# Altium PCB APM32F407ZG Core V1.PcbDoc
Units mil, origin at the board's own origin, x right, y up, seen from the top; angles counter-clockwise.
Board outline 2360 x 2125 mil, 2 copper layers (Top Layer, Bottom Layer); 40 components, 124 nets, 388 pads, 216 vias.
Unrouted connection lines stored in the file: 595.
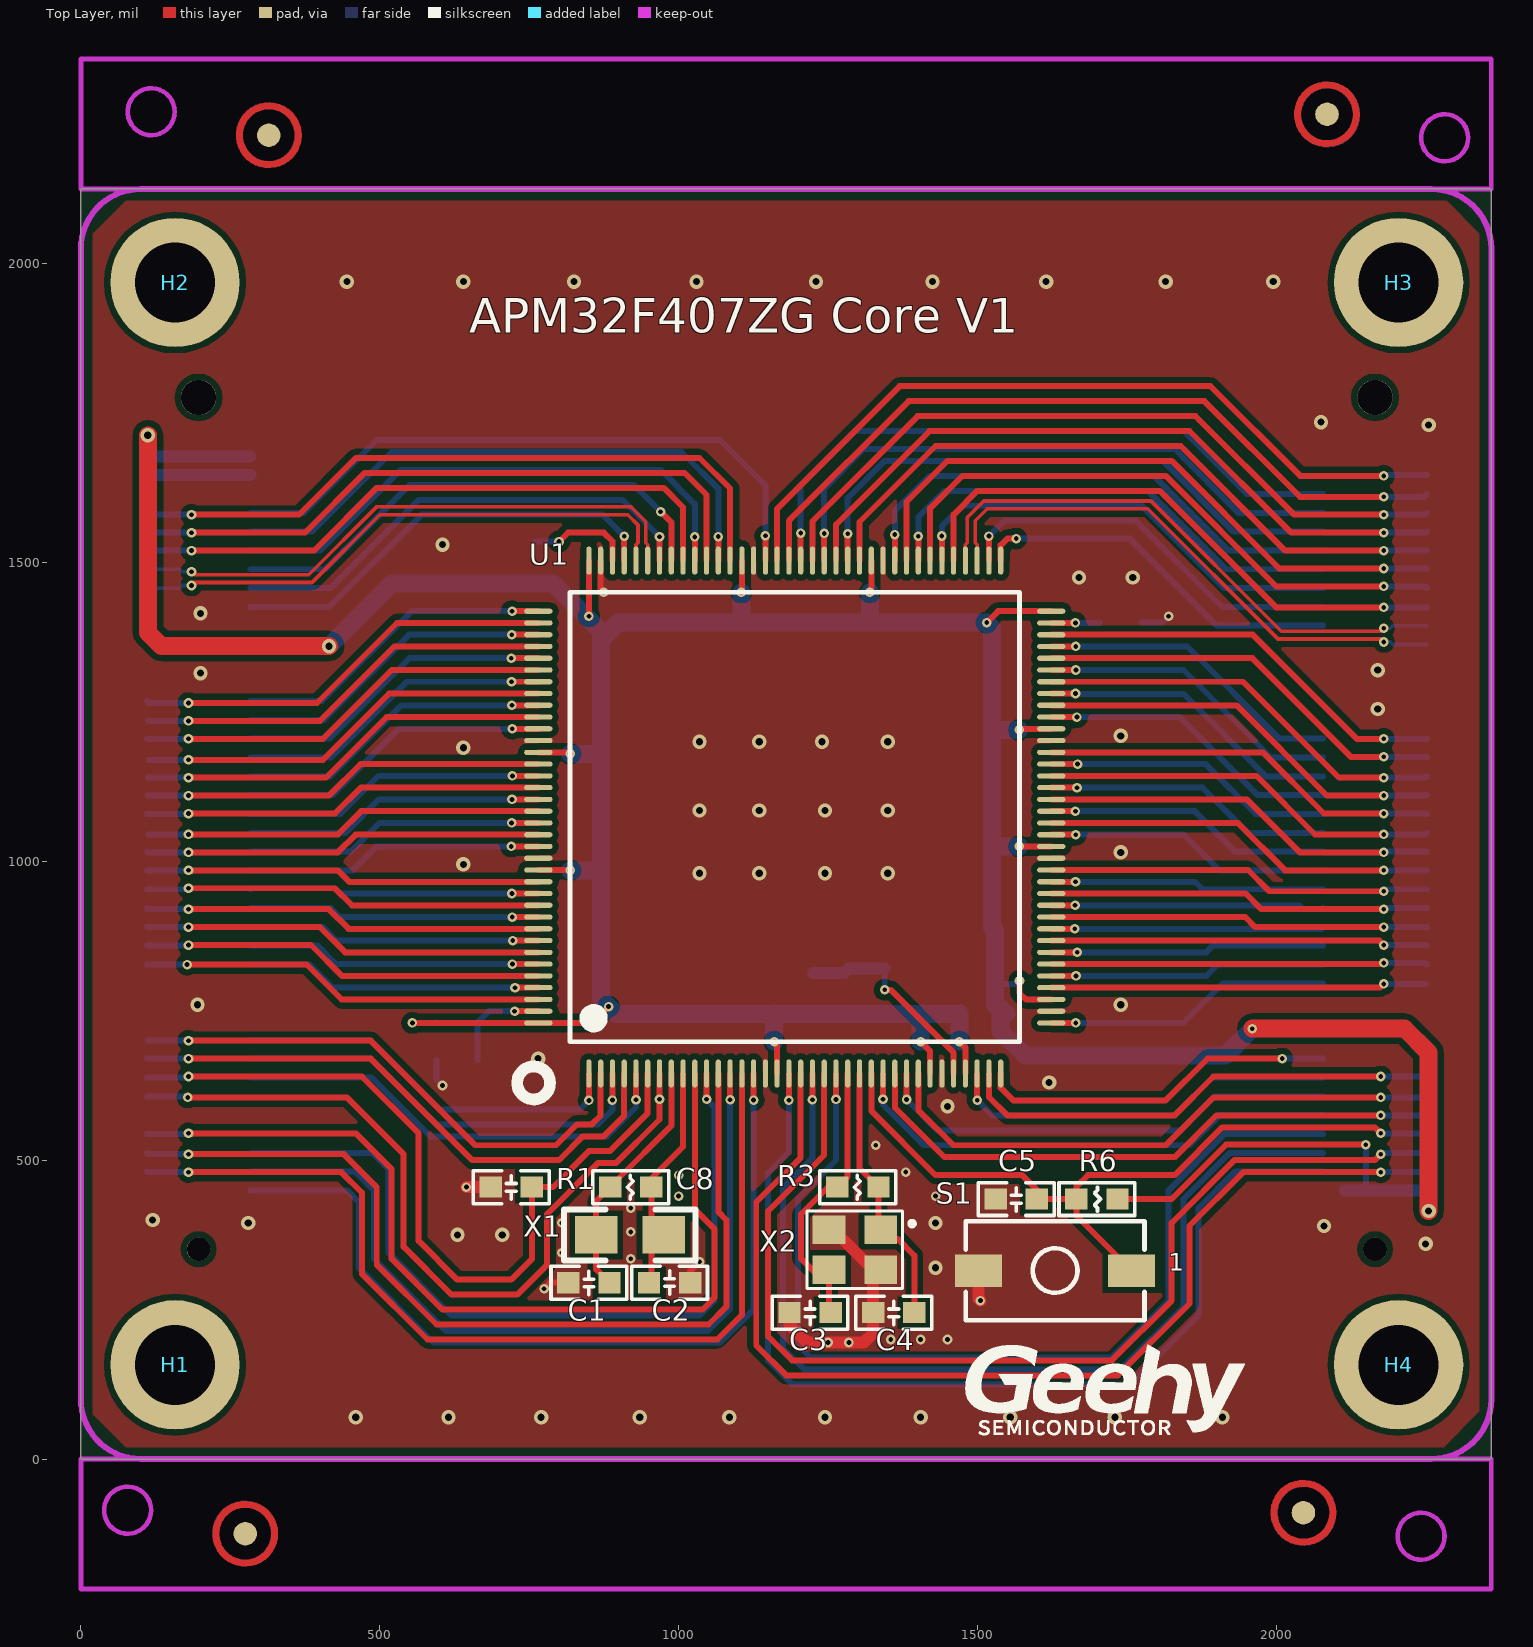
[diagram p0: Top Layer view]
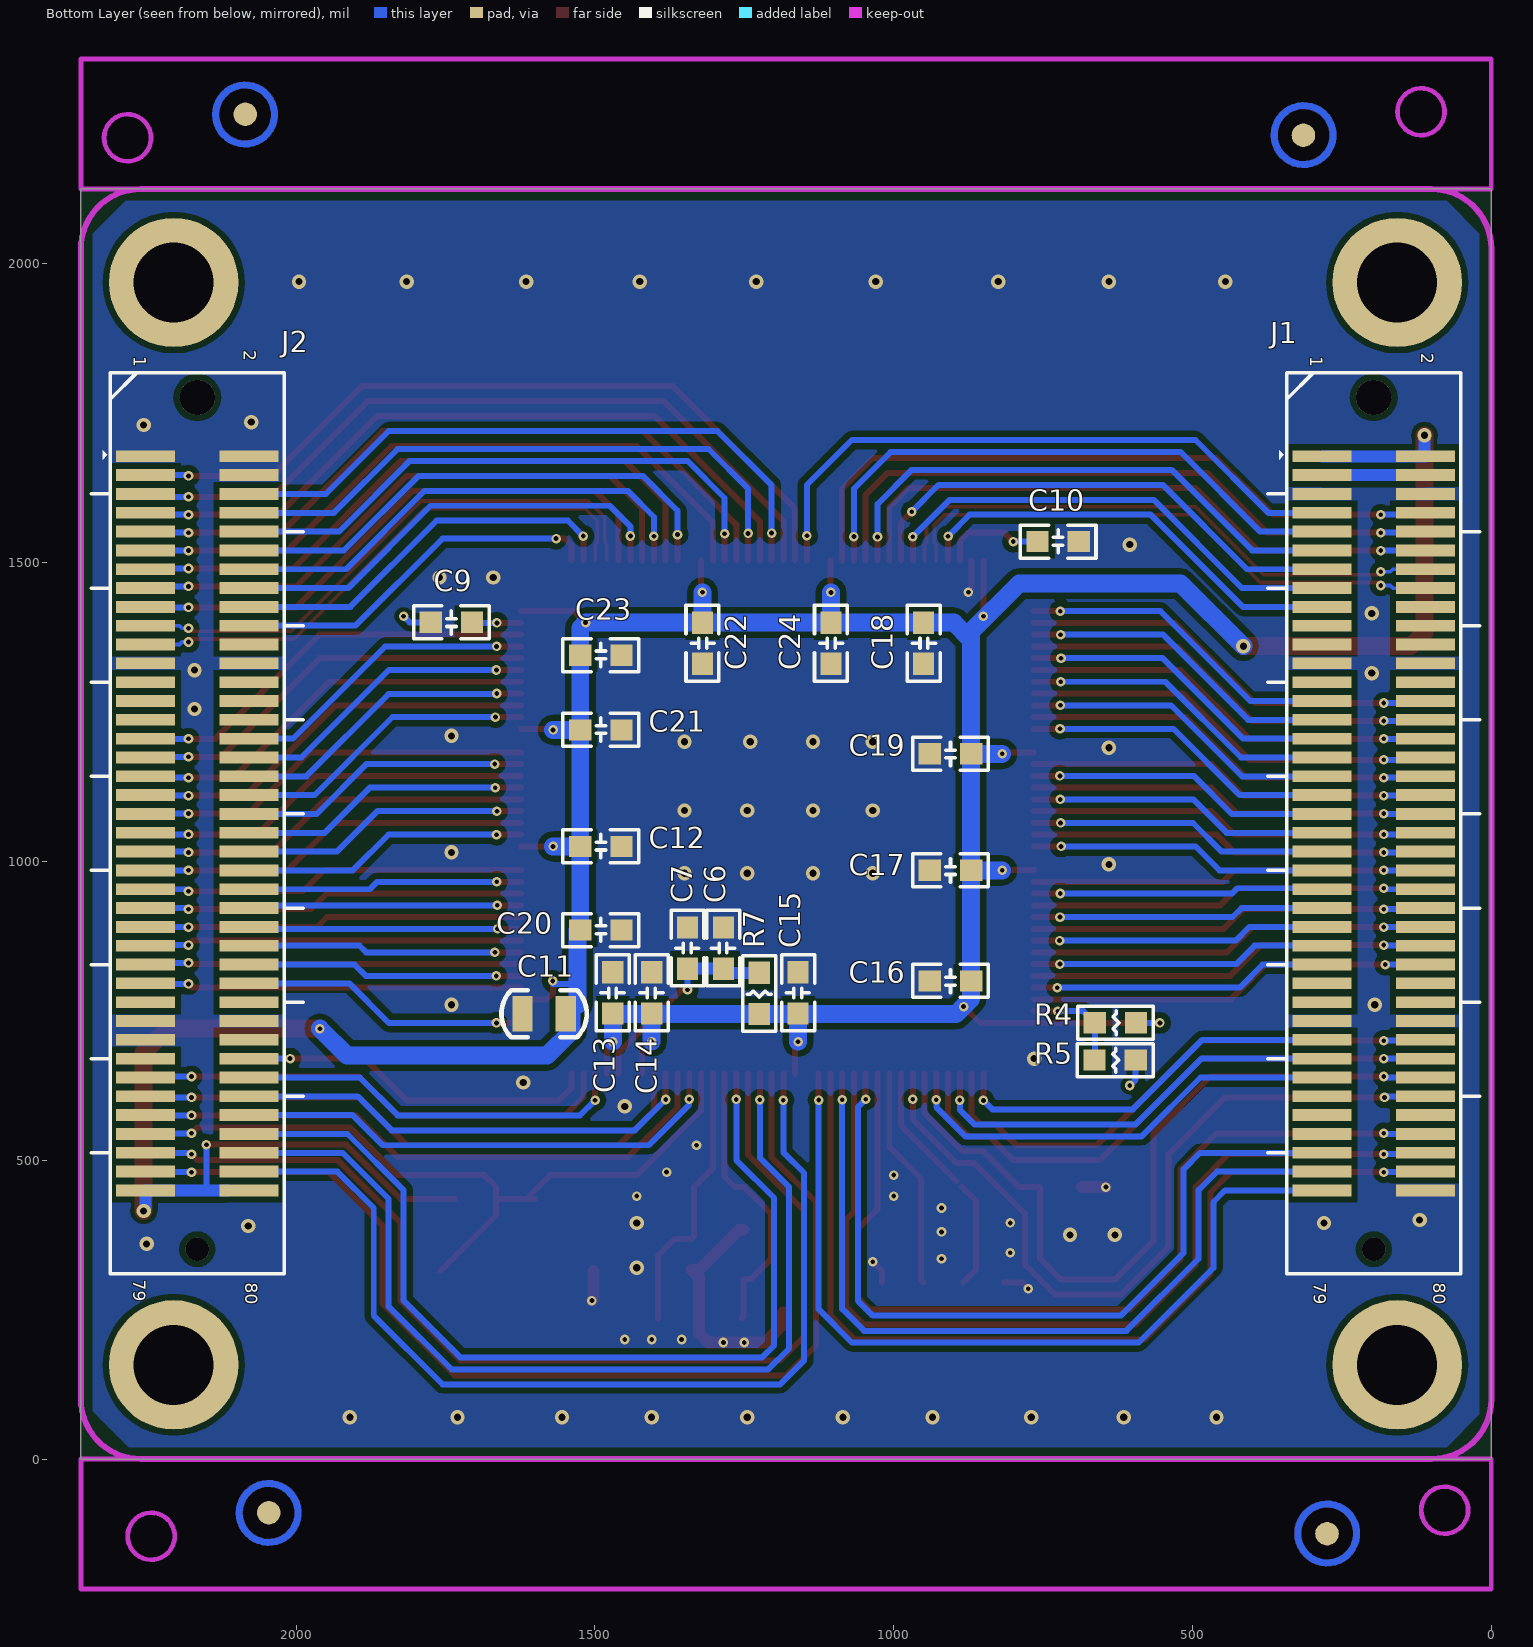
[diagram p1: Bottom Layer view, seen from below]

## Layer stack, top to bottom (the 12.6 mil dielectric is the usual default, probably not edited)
Top Layer: signal copper 1.4
Dielectric: dielectric 12.6, FR-4, Dk 4.8
Bottom Layer: signal copper 1.4

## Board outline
0,2125 0,0 2360,0 2360,2125

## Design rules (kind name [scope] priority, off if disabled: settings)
Clearance Clearance_1 [IsRegion] p1: gap=10
Clearance [All] p2: gap=6
DiffPairsRouting [All] p1: maxlimit=10 minlimit=1 mostfreqgap=7 maxuncoupledlength=500
HoleSize [All] p1: absolutevalues=TRUE maxlimit=1000 minlimit=1 maxpercent=80.000 minpercent=20.000
MinimumSolderMaskSliver [All] p1: minsoldermaskwidth=0.1
PolygonConnect [All] p1: connectstyle=Direct reliefconductorwidth=10 reliefentries=4 polygonreliefangle="90 Angle" airgapwidth=10
RoutingVias [All] p1: holewidth=8 width=16 viastyle="Through Hole" minholewidth=1 minwidth=1 maxholewidth=28 maxwidth=50
SilkToSilkClearance [All] p1: silktosilkclearance=1
SilkToSolderMaskClearance [IsPad] p1: minsilkscreentomaskgap=0.1 clearancetoexposedcopper=TRUE
SolderMaskExpansion [All] p1: expansion=4
Width [All] p1: maxlimit=100 minlimit=1 preferedwidth=10 minimp=50.000000 maximp=50.000000 favimp=50.000000
23 further rules are at their usual default settings.

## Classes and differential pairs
component class 02_Connect: H1 H2 H3 H4 J1 J2
differential pair class "New Class": OTG_FS OTG_HS
component class 01_MCU: C1 C2 C3 C4 C5 C6 C7 C8 C9 C10 C11 C12 C13 C14 C15 C16 C17 C18 C19 C20 C21 C22 C23 C24 J3 R1 R3 R4 R5 R6 R7 S1 U1 U4 X1 X2
differential pair OTG_FS: +PA12_OTG_FS_P -PA11_OTG_FS_N
differential pair OTG_HS: +PB15_OTG_HS_P -PB14_OTG_HS_N

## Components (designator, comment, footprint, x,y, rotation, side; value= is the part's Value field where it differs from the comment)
C1 "10pF" C0603 850,294.98 r180 top
C2 "10pF" C0603 985,294.98 r0 top
C3 "20pF" C0603 1220,244.98 r180 top
C4 "20pF" C0603 1360,244.98 r180 top
C5 "100nF" C0603 1565,434.98 r180 top
C6 "1uF" C0603 1285,854.98 r90 bottom
C7 "10nF" C0603 1345,854.98 r90 bottom
C8 "100nF" C0603 720,454.98 r180 top
C9 "2.2uF" C0603 1740,1399.98 r0 bottom
C10 "2.2uF" C0603 725,1534.98 r180 bottom
C11 "4.7uF" C0805 1585,744.98 r0 bottom
C12 "100nF" C0603 1490,1024.98 r180 bottom
C13 "100nF" C0603 1470,779.98 r90 bottom
C14 "100nF" C0603 1405,779.98 r90 bottom
C15 "100nF" C0603 1160,779.98 r90 bottom
C16 "100nF" C0603 905,799.98 r0 bottom
C17 "100nF" C0603 905,984.98 r0 bottom
C18 "100nF" C0603 950,1364.98 r270 bottom
C19 "100nF" C0603 905,1179.98 r0 bottom
C20 "100nF" C0603 1490,884.98 r180 bottom
C21 "100nF" C0603 1490,1219.98 r180 bottom
C22 "100nF" C0603 1490,1344.98 r180 bottom
C23 "100nF" C0603 1320,1364.98 r270 bottom
C24 "100nF" C0603 1105,1364.98 r270 bottom
H1 "Value" THC5R5D3R4-M3-PTH#1 975,3804.98 r0 top
H2 "Value" THC5R5D3R4-M3-PTH#2 157.48,2792.5 r0 top
H3 "Value" THC5R5D3R4-M3-PTH#3 1570,3814.98 r0 top
H4 "Value" THC5R5D3R4-M3-PTH#4 1845,3814.98 r0 top
J1 "61082-081402LF" B2B2X40R-0R8-SM-Z-H3R7 196.81,1063.57 r270 bottom locked
J2 "61082-081402LF" B2B2X40R-0R8-SM-Z-H3R7 2165.31,1063.57 r270 bottom
R1 "NC" R0603 920,454.98 r180 top
R3 "NC" R0603 1300,454.98 r180 top
R4 "NC" R0603 629,729.98 r180 bottom
R5 "10K" R0603 629.55,667.54 r180 bottom
R6 "10K" R0603 1700,434.98 r0 top
R7 "0R" R0603 1225,778.98 r270 bottom
S1 "434121025816" SW-SMD-6X3R8X2R5-1 1630,314.98 r180 top
U1 "APM32F407ZG" LQFP-144M 850,644.98 r90 top locked
X1 "32.768KHz" R1206 975,374.98 r180 top
X2 "8MHz" XTAL3225 1295,349.98 r180 top

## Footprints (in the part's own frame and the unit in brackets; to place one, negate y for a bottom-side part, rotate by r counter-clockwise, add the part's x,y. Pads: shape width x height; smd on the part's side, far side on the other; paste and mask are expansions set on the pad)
B2B2X40R-0R8-SM-Z-H3R7 [mm]
  rect 0.5x2.5 smd: 1(-15.6,-2.2) 2(-15.6,2.2) 3(-14.8,-2.2) 4(-14.8,2.2) 5(-14,-2.2) 6(-14,2.2) 7(-13.2,-2.2) 8(-13.2,2.2) 9(-12.4,-2.2) 10(-12.4,2.2) 11(-11.6,-2.2) 12(-11.6,2.2) 13(-10.8,-2.2) 14(-10.8,2.2) 15(-10,-2.2) 16(-10,2.2) 17(-9.2,-2.2) 18(-9.2,2.2) 19(-8.4,-2.2) 20(-8.4,2.2) 21(-7.6,-2.2) 22(-7.6,2.2) 23(-6.8,-2.2) 24(-6.8,2.2) 25(-6,-2.2) 26(-6,2.2) 27(-5.2,-2.2) 28(-5.2,2.2) 29(-4.4,-2.2) 30(-4.4,2.2) 31(-3.6,-2.2) 32(-3.6,2.2) 33(-2.8,-2.2) 34(-2.8,2.2) 35(-2,-2.2) 36(-2,2.2) 37(-1.2,-2.2) 38(-1.2,2.2) 39(-0.4,-2.2) 40(-0.4,2.2) 41(0.4,-2.2) 42(0.4,2.2) 43(1.2,-2.2) 44(1.2,2.2) 45(2,-2.2) 46(2,2.2) 47(2.8,-2.2) 48(2.8,2.2) 49(3.6,-2.2) 50(3.6,2.2) 51(4.4,-2.2) 52(4.4,2.2) 53(5.2,-2.2) 54(5.2,2.2) 55(6,-2.2) 56(6,2.2) 57(6.8,-2.2) 58(6.8,2.2) 59(7.6,-2.2) 60(7.6,2.2) 61(8.4,-2.2) 62(8.4,2.2) 63(9.2,-2.2) 64(9.2,2.2) 65(10,-2.2) 66(10,2.2) 67(10.8,-2.2) 68(10.8,2.2) 69(11.6,-2.2) 70(11.6,2.2) 71(12.4,-2.2) 72(12.4,2.2) 73(13.2,-2.2) 74(13.2,2.2) 75(14,-2.2) 76(14,2.2) 77(14.8,-2.2) 78(14.8,2.2) 79(15.6,-2.2) 80(15.6,2.2)
  round 1.5 hole 1.5: 81(-18.1,0)
  round 1 hole 1: 82(18.1,0)
  silkscreen extent -19.16,-4.5 19.15,4.5, body extent -18.9,-3 18.9,3, height 3.7
C0603 [mm]
  rect 0.95x0.9 smd: 1(-0.875,0) 2(0.875,0)
  silkscreen extent -1.61,-0.7 1.61,0.7, body extent -0.76,-0.41 0.76,0.36, height 0.78
C0805 [mm]
  rect 0.86x1.5 smd: 1(-0.92,0) 2(0.92,0)
  silkscreen extent -1.81,-1 1.81,1, body extent -1,-0.62 1,0.63, height 0.78
LQFP-144M [mm]
  oval 1.2x0.22 smd: 1(0,0) 2(0,-0.5) 3(0,-1) 4(0,-1.5) 5(0,-2) 6(0,-2.5) 7(0,-3) 8(0,-3.5) 9(0,-4) 10(0,-4.5) 11(0,-5) 12(0,-5.5) 13(0,-6) 14(0,-6.5) 15(0,-7) 16(0,-7.5) 17(0,-8) 18(0,-8.5) 19(0,-9) 20(0,-9.5) 21(0,-10) 22(0,-10.5) 23(0,-11) 24(0,-11.5) 25(0,-12) 26(0,-12.5) 27(0,-13) 28(0,-13.5) 29(0,-14) 30(0,-14.5) 31(0,-15) 32(0,-15.5) 33(0,-16) 34(0,-16.5) 35(0,-17) 36(0,-17.5) 73(21.8,-17.5) 74(21.8,-17) 75(21.8,-16.5) 76(21.8,-16) 77(21.8,-15.5) 78(21.8,-15) 79(21.8,-14.5) 80(21.8,-14) 81(21.8,-13.5) 82(21.8,-13) 83(21.8,-12.5) 84(21.8,-12) 85(21.8,-11.5) 86(21.8,-11) 87(21.8,-10.5) 88(21.8,-10) 89(21.8,-9.5) 90(21.8,-9) 91(21.8,-8.5) 92(21.8,-8) 93(21.8,-7.5) 94(21.8,-7) 95(21.8,-6.5) 96(21.8,-6) 97(21.8,-5.5) 98(21.8,-5) 99(21.8,-4.5) 100(21.8,-4) 101(21.8,-3.5) 102(21.8,-3) 103(21.8,-2.5) 104(21.8,-2) 105(21.8,-1.5) 106(21.8,-1) 107(21.8,-0.5) 108(21.8,0)
  oval 0.22x1.2 smd: 37(2.15,-19.65) 38(2.65,-19.65) 39(3.15,-19.65) 40(3.65,-19.65) 41(4.15,-19.65) 42(4.65,-19.65) 43(5.15,-19.65) 44(5.65,-19.65) 45(6.15,-19.65) 46(6.65,-19.65) 47(7.15,-19.65) 48(7.65,-19.65) 49(8.15,-19.65) 50(8.65,-19.65) 51(9.15,-19.65) 52(9.65,-19.65) 53(10.15,-19.65) 54(10.65,-19.65) 55(11.15,-19.65) 56(11.65,-19.65) 57(12.15,-19.65) 58(12.65,-19.65) 59(13.15,-19.65) 60(13.65,-19.65) 61(14.15,-19.65) 62(14.65,-19.65) 63(15.15,-19.65) 64(15.65,-19.65) 65(16.15,-19.65) 66(16.65,-19.65) 67(17.15,-19.65) 68(17.65,-19.65) 69(18.15,-19.65) 70(18.65,-19.65) 71(19.15,-19.65) 72(19.65,-19.65) 109(19.65,2.15) 110(19.15,2.15) 111(18.65,2.15) 112(18.15,2.15) 113(17.65,2.15) 114(17.15,2.15) 115(16.65,2.15) 116(16.15,2.15) 117(15.65,2.15) 118(15.15,2.15) 119(14.65,2.15) 120(14.15,2.15) 121(13.65,2.15) 122(13.15,2.15) 123(12.65,2.15) 124(12.15,2.15) 125(11.65,2.15) 126(11.15,2.15) 127(10.65,2.15) 128(10.15,2.15) 129(9.65,2.15) 130(9.15,2.15) 131(8.65,2.15) 132(8.15,2.15) 133(7.65,2.15) 134(7.15,2.15) 135(6.65,2.15) 136(6.15,2.15) 137(5.65,2.15) 138(5.15,2.15) 139(4.65,2.15) 140(4.15,2.15) 141(3.65,2.15) 142(3.15,2.15) 143(2.65,2.15) 144(2.15,2.15)
  silkscreen extent -1.1,-18.3 20.45,3.05
R0603 [mm]
  rect 0.95x0.9 smd: 1(-0.875,0) 2(0.875,0)
  silkscreen extent -1.61,-0.7 1.61,0.7, body extent -0.82,-0.43 0.88,0.37, height 0.56
R1206 [mm]
  rect 1.8x1.6 smd: 1(0,0) 2(2.865,0)
  silkscreen extent -1.36,-1.08 4.24,1.08
SW-SMD-6X3R8X2R5-1 [mm]
  rect 2x1.4 smd: 1(-3.25,0) 2(3.25,0)
  silkscreen extent -3.8,-2.1 3.8,2.1, body extent -3.65,-1.96 3.65,1.94, height 2.5
THC5R5D3R4-M3-PTH#1 [mm]
  round 5.5 hole 3.4: 1(-20.765,-92.647)
THC5R5D3R4-M3-PTH#2 [mm]
  round 5.5 hole 3.4: 1(0,-20.93)
THC5R5D3R4-M3-PTH#3 [mm]
  round 5.5 hole 3.4: 1(16.122,-46.901)
THC5R5D3R4-M3-PTH#4 [mm]
  round 5.5 hole 3.4: 1(9.137,-92.901)
XTAL3225 [mm]
  rect 1.4x1.2 smd: 1(-1.1,-0.85) 2(1.1,-0.85) 3(1.1,0.85) 4(-1.1,0.85)
  silkscreen extent -2.48,-1.65 2.04,1.65, body extent -1.63,-1.28 1.57,1.22, height 0.91

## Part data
C1 C2: library part 101CC-00365BE.01, "SMD,电容量10pF,额定电压50V,偏差±1pF,材质C0G,0603"
C3 C4: library part 101CC-00471BW.01, "安装方式SMD,电容量20pF,额定电压50V,偏差±5%,材质NPO,0603"
C5 C8 C12 C13 C14 C15 C16 C17 C18 C19 C20 C21 C22 C23 C24: library part 101CC-00003IA.01, "SMD,电容量100nF,额定电压50V,偏差±10%,材质X7R,0603"
C6: library part 101CC-00005IA.01, "SMD,电容量1uF,额定电压50V,偏差±10%,材质X5R,0603"
C7: library part 101CC-00002IA.01, "SMD,电容量10nF,额定电压50V,偏差±10%,材质X7R,0603"
C9 C10: library part 101CC-00009IA.01, "SMD,电容量2.2uF,额定电压25V,偏差±10%,材质X5R,0603"
C11: library part 101CC-00357OD.01, "SMD,电容量4.7uF,额定电压50V,精度±10%,材质X5R,0805"
H1 H2 H3 H4: library part M3-PTH
J1 J2: library part 101NH-00010CO.01, "SMD,座子,封装脚距0.80mm,180度,引脚数目2x40PIN,塑高/针长3.7mm/无,白色"
R1 R3 R4 R7: library part 101RC-00012IA.01, "SMD,阻值0R,精度±1%,0603,额定功率1/10W"
R5 R6: library part 101RC-00003IA.01, "SMD,阻值10K,精度±1%,0603,额定功率1/10W"
S1: library part 101SA-00035BV.01, "安装方式SMD,封装尺寸6.00x3.80x2.50mm,2PIN,装配角度180度,黑色"
U1: library part APM32F407Z
X1: library part XTAL, "Crystal Oscillator"
X2: library part 101XB-00001AN.01, "SMD,材质陶瓷外壳,封装外壳3225,精度±10ppm,震荡频率8MHz"

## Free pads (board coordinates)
  round 39.37 smd: 1(275,-125) 1(314.48,2214.87) 1(2045.52,-89.87) 1(2085,2250)
  round 39.37 smd far side: 6(275,-125) 6(314.48,2214.87) 6(2045.52,-89.87) 6(2085,2250)

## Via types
v1: diameter 16, hole 8, Top Layer to Bottom Layer, 156 vias
v2: diameter 24, hole 12, Top Layer to Bottom Layer, 60 vias

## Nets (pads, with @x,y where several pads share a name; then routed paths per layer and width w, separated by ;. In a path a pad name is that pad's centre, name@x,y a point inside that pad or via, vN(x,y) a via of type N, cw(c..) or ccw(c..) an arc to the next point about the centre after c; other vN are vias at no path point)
+3V3: C11.1 C12.1 C13.1 C14.1 C15.1 C16.1 C17.1 C18.1 C19.1 C20.1 C21.1 C22.1 C23.1 C24.1 J1.1 J1.2 J2.79 J2.80 R4.2 R6.2 R7.2 U1.17 U1.30 U1.33 U1.39 U1.52 U1.62 U1.72 U1.84 U1.95 U1.108 U1.121 U1.131 U1.144 | length 7356.3
  Top Layer w10: v1(554.65,729.63) U1.144 855.65,729.63 v1(883,756.98) ; U1.131 817.95,985.54 v1(818.5,984.98) ; U1.121 816.1,1182.39 v1(818.5,1179.98) ; v1(850,1409.98) U1.108 ; v1(1105,1449.98) 1105.91,1450.89 U1.95 ; v1(1160,698.13) 1164.96,693.17 U1.17 ; v1(1320,1450.1) 1322.44,1452.54 U1.84 ; v1(1405,698.13) 1420.87,682.27 U1.30 ; v1(1470,698.13) 1479.92,688.21 U1.33 ; v1(1515.55,1399.43) 1534.72,1418.61 U1.72 ; v1(1570,1024.98) 1570.08,1024.91 U1.52 ; v1(1570,1219.98) 1571.77,1221.76 U1.62 ; v1(1570.47,799.98) 1570.47,779.51 1580.98,769 U1.39 ; R6.2 1825,434.98 1916,525.98 v1(2150,525.98)
  Top Layer w30: v2(111.97,1713.02) 111.97,1383.02 135,1359.98 v2(415,1359.98) ; v1(1960,719.98) 2215,719.98 2255,679.98 v2(2255,414.98)
  Bottom Layer w10: v1(554.65,729.63) 594.2,729.63 R4.2 ; 1529.45,794.98 v1@1570.47,794.98 ; 2150,449.39 v1(2150,525.98)
  Bottom Layer w20: v2(111.97,1713.02) 111.97,1679.51 J1.2 J1.1 ; J2.80@2115,449.39 2150,449.39 J2.79 2251.93,418.06 v2(2255,414.98)
  Bottom Layer w30: v2(415,1359.98) 520,1464.98 790,1464.98 870.55,1384.43 870.55,1370.54 ; v1(818.5,984.98) C17.1 ; v1(818.5,1179.98) C19.1 ; v1(1105,1449.98) C24.1 ; v1(1160,698.13) C15.1@1160,744.54 ; C15.1 C15.1@1160,744.54 ; v1(1320,1450.1) C23.1 ; v1(1405,698.13) C14.1@1405,744.54 ; C14.1 C14.1@1405,744.54 ; v1(1470,698.13) C13.1 1469,744.54 C14.1@1405,744.54 ; C11.1 C11.1@1538.78,754.98 ; v1(1570,1024.98) C12.1 ; v1(1570,1219.98) C21.1 ; v1(1960,719.98) 1915,674.98 1580,674.98 1538.78,716.2 C11.1@1538.78,754.98 ; C17.1 870.55,769.43 v1(883,756.98) 895.45,744.54 C15.1@1160,744.54 ; C17.1 C19.1 ; C19.1 870.55,1370.54 ; 870.55,1370.54 899.45,1399.43 C18.1 C24.1 ; C24.1 C23.1 ; C15.1@1160,744.54 C14.1@1405,744.54 ; C23.1 v1(1515.55,1399.43) 1524.45,1390.54 C22.1 C21.1 ; C12.1 1524.45,890.16 1529.44,885.16 1529.45,884.98 1529.45,794.98 1529.45,759.43 1531.89,761.87 C11.1@1538.78,754.98 ; C12.1 C21.1
+5V: J1.3 J1.4 | length 173.2
  Bottom Layer w20: J1.4 J1.3
BOOT0: J1.52 U1.138 | length 672.3
  Top Layer w10: v1(180,889.98) 400,889.98 442.24,847.74 U1.138
  Bottom Layer w10: J1.52@110.55,889.98 v1(180,889.98)
GND: C1.2 C2.2 C3.2 C4.2 C5.2 C6.2 C7.2 C8.2 C9.2 C10.2 C11.2 C12.2 C13.2 C14.2 C15.2 C16.2 C17.2 C18.2 C19.2 C20.2 C21.2 C22.2 C23.2 C24.2 J1.5 J1.6 J1.23 J1.24 J1.61 J1.62 J1.80 J2.1 J2.2 J2.4 J2.23 J2.24 J2.61 J2.62 J2.63 R5.2 S1.2 U1.16 U1.31 U1.38 U1.51 U1.61 U1.83 U1.94 U1.107 U1.120 U1.130 X2.2 X2.4 | length 734.5
  Top Layer w10: v1(775,284.98) 785,294.98 C1.2 ; U1.107 869.68,1455.42 v1(875,1450.1) ; C2.2 1019.45,314.43 v1(1035,329.98)
  Top Layer w20: v1(645,455) C8.2 ; C3.2 1185.55,224.43 1215,194.98 1310,194.98 1325.55,210.54 C4.2 1325.55,303.76 X2.4 1325.5,316.52 1258.57,383.45 X2.2 ; S1.2 1502.05,267.94 v1(1505,264.98)
  Bottom Layer w10: R5.2 595.1,634.88 v1(605.05,624.93) ; C9.2 1810,1399.98 v1(1820,1409.98)
  other v1: 1250,194.98 1285,194.98 1355,200 1405,200 1450,200 920,335 805,345 920,380 805,395 920,420 1000,440 1430,440 1000,475 1380,480 1330,525
  other v2: 460,69.98 615,69.98 770,69.98 935,69.98 1085,69.98 1245,69.98 1405,69.98 1555,69.98 1730,69.98 1910,69.98 1430,319.98 2250,359.98 630,374.98 705,374.98 2080,389.98 280,394.98 1430,394.98 120,399.98 1450,589.98 1620,629.98 765,669.98 195,759.98 1740,759.98 1035,979.98 1135,979.98 1245,979.98 1350,979.98 640,994.98 1740,1014.98 1035,1084.98 1135,1084.98 1245,1084.98 1350,1084.98 640,1189.98 1035,1199.98 1135,1199.98 1240,1199.98 1350,1199.98 1740,1209.98 2170,1254.98 200,1314.98 2170,1319.98 200,1414.98 1670,1474.98 1760,1474.98 605,1529.98 2255,1729.98 2075,1734.98 445,1969.98 640,1969.98 825,1969.98 1030,1969.98 1230,1969.98 1425,1969.98 1615,1969.98 1815,1969.98 1995,1969.98
NetC6_1: C6.1 C7.1 R7.1 U1.32 | length 352.1
  Top Layer w10: v1(1345,784.98) 1355,784.98 1460.24,679.75 U1.32
  Bottom Layer w10: v1(1345,784.98) C7.1
  Bottom Layer w20: R7.1 1277.9,813.43 C6.1 C7.1
NetC9_1: C9.1 U1.71 | length 82.4
  Top Layer w10: U1.71 v1(1663.94,1398.92)
  Bottom Layer w10: v1(1663.94,1398.92) 1704.49,1398.92 C9.1
NetC10_1: C10.1 U1.106 | length 174.4
  Top Layer w10: v1(800,1534.98) 815,1549.98 875,1549.98 889.37,1535.61 U1.106
  Bottom Layer w10: C10.1 v1(800,1534.98)
PA0_CAMRE_PW: J2.68 U1.34 | length 660.5
  Top Layer w10: v1(1499.61,600.38) U1.34
  Bottom Layer w10: v1(1499.61,600.38) 1525,574.98 1830,574.98 1893.39,638.37 J2.68
PA1_RMII_REF_CLK: J2.67 U1.35 | length 812.2
  Top Layer w10: U1.35 1519.29,605.69 1550,574.98 1830,574.98 1895,639.98 v1(2175,639.98)
  Bottom Layer w10: v1(2175,639.98) 2250.31,639.98 J2.67
PA2_ETH_MDIO: J2.66 U1.36 | length 601.5
  Top Layer w10: U1.36 1538.98,621.01 1560,599.98 1815,599.98 1885,669.98 v1(2010,669.98)
  Bottom Layer w10: v1(2010,669.98) 2078.58,669.98 J2.66
PA3_SDR_CKE: J2.58 U1.37 | length 482.5
  Top Layer w10: U1.37 v1(1664.65,729.63)
  Bottom Layer w10: v1(1664.65,729.63) 1844.65,729.63 1910.87,795.85 J2.58
PA4_DCMI_HS: J2.57 U1.40 | length 630.1
  Top Layer w10: U1.40 2173.7,788.69 v1(2180,794.98)
  Bottom Layer w10: v1(2180,794.98) J2.57@2251.06,794.98
PA5_KEY4: J2.56 U1.41 | length 462.9
  Top Layer w10: U1.41 v1(1665,808.37)
  Bottom Layer w10: v1(1665,808.37) 1883.39,808.37 1902.36,827.35 J2.56
PA6_DCMI_PIXCK: J2.55 U1.42 | length 630.2
  Top Layer w10: U1.42 2178.07,828.06 v1(2180,829.98)
  Bottom Layer w10: v1(2180,829.98) 2249.29,829.98 J2.55
PA7_RMII_CRS_DV: J2.54 U1.43 | length 459.7
  Top Layer w10: U1.43 v1(1667.24,847.74)
  Bottom Layer w10: v1(1667.24,847.74) 1882.76,847.74 1893.86,858.84 J2.54
PA8_CAMER_XCLK: J1.12 U1.100 | length 1043.6
  Top Layer w10: v1(185,1519.98) 390,1519.98 495,1624.98 975,1624.98 1007.48,1592.5 U1.100
  Bottom Layer w10: J1.12 110.47,1519.98 v1(185,1519.98)
PA9_USART1_TX: J1.13 U1.101 | length 852.8
  Top Layer w10: v1(970,1584.98) 987.8,1567.19 U1.101
  Bottom Layer w10: J1.13 408.78,1488.76 550,1629.98 925,1629.98 v1(970,1584.98)
PA10_USART1_RX: J1.15 U1.102 | length 811.3
  Top Layer w10: U1.102 v1(968.11,1543.09)
  Bottom Layer w10: J1.15 417.28,1457.27 565,1604.98 906.22,1604.98 v1(968.11,1543.09)
PA11_OTG_FS_N: J1.14 U1.103 | length 962.4
  Top Layer w6: v1(185,1484.52) 190,1479.52 381.15,1479.52 494.62,1592.98 920.38,1592.98 924.19,1589.18 945.08,1568.29 945.08,1533.33 948.43,1529.98 U1.103
  Bottom Layer w6: J1.14 165,1488.76 169.25,1484.52 v1(185,1484.52)
PA12_OTG_FS_P: J1.16 U1.104 | length 940.8
  Top Layer w6: v1(185,1461.52) 190,1466.52 386.53,1466.52 500,1579.98 915,1579.98 932.08,1562.9 932.08,1533.33 928.74,1529.98 U1.104
  Bottom Layer w6: J1.16 165,1457.27 169.25,1461.52 v1(185,1461.52)
PA13_SWDIO: J1.17 U1.105 | length 745.2
  Top Layer w10: U1.105 v1(909.06,1544.04)
  Bottom Layer w10: J1.17 415.79,1425.77 570,1579.98 873.11,1579.98 v1(909.06,1544.04)
PA14_SWCLK: J1.27 U1.109 | length 544.2
  Top Layer w10: v1(721.38,1418.61) U1.109
  Bottom Layer w10: J1.27 403.31,1268.29 553.62,1418.61 v1(721.38,1418.61)
PA15_TDI: J1.28 U1.110 | length 712
  Top Layer w10: v1(180,1264.98) 395,1264.98 528.94,1398.92 U1.110
  Bottom Layer w10: J1.28 113.5,1264.98 v1(180,1264.98)
PB0_KEY1: J2.51 U1.46 | length 635.4
  Top Layer w10: U1.46 1948.19,906.8 1965,889.98 v1(2180,889.98)
  Bottom Layer w10: v1(2180,889.98) 2251.57,889.98 J2.51
PB1_KEY2: J2.50 U1.47 | length 458.5
  Top Layer w10: U1.47 v1(1663.5,926.48)
  Bottom Layer w10: v1(1663.5,926.48) 2038.5,926.48 2045,919.98 2076.85,919.98 J2.50
PB2_BOOT1: J2.49 U1.48 | length 639.9
  Top Layer w10: U1.48 1948.82,946.17 1975,919.98 v1(2180,919.98)
  Bottom Layer w10: v1(2180,919.98) 2181.85,921.83 J2.49
PB3_SPI_SCK: J1.47 U1.133 | length 486.3
  Top Layer w10: v1(721.18,946.17) U1.133
  Bottom Layer w10: J1.47 285.08,954.98 425,954.98 433.82,946.17 v1(721.18,946.17)
PB4_SPI_MISO: J1.48 U1.134 | length 667.6
  Top Layer w10: v1(180,954.98) 425,954.98 453.5,926.48 U1.134
  Bottom Layer w10: J1.48 178.35,953.33 v1(180,954.98)
PB5_SPI_MOSI: J1.49 U1.135 | length 488.2
  Top Layer w10: v1(721.81,906.8) U1.135
  Bottom Layer w10: J1.49 418.15,921.83 433.19,906.8 v1(721.81,906.8)
PB6_DCMI_D5: J1.50 U1.136 | length 669.5
  Top Layer w10: v1(180,919.98) 415,919.98 447.87,887.11 U1.136
  Bottom Layer w10: J1.50 112.05,919.98 v1(180,919.98)
PB7_DCMI_VS: J1.51 U1.137 | length 491.4
  Top Layer w10: v1(722.44,867.43) U1.137
  Bottom Layer w10: J1.51 404.65,890.34 427.56,867.43 v1(722.44,867.43)
PB8_I2C1_SCL: J1.53 U1.139 | length 494.7
  Top Layer w10: v1(721.93,828.06) U1.139
  Bottom Layer w10: J1.53 396.14,858.84 426.93,828.06 v1(721.93,828.06)
PB9_I2C1_SDA: J1.54 U1.140 | length 677
  Top Layer w10: v1(180,859.98) 385,859.98 436.61,808.37 U1.140
  Bottom Layer w10: J1.54 178.86,858.84 v1(180,859.98)
PB10_USART3_TX: J2.32 U1.69 | length 519
  Top Layer w10: U1.69 v1(1664.57,1359.55)
  Bottom Layer w10: v1(1664.57,1359.55) 1850.94,1359.55 2005.2,1205.3 J2.32
PB11_USART3_RX: J2.31 U1.70 | length 700.6
  Top Layer w10: U1.70 1960.75,1379.24 2135,1204.98 v1(2180,1204.98)
  Bottom Layer w10: v1(2180,1204.98) 2251.61,1204.98 J2.31
PB12_CAN2_RX: J2.20 U1.73 | length 630.4
  Top Layer w10: U1.73 1538.98,1528.96 1550,1539.98 v1(1565,1539.98)
  Bottom Layer w10: v1(1565,1539.98) 1755,1539.98 1900.71,1394.28 J2.20
PB13_CAN2_TX: J2.18 U1.74 | length 670.8
  Top Layer w10: U1.74 v1(1519.29,1544.28)
  Bottom Layer w10: v1(1519.29,1544.28) 1545,1569.98 1765,1569.98 1909.21,1425.77 J2.18
PB14_OTG_HS_N: J2.21 U1.75 | length 926.2
  Top Layer w6: U1.75 1499.61,1529.98 1496.26,1533.33 1496.26,1569.98 1516.26,1589.98 1785,1589.98 2003,1371.98 2175.04,1371.98 v1(2180,1367.03)
  Bottom Layer w6: v1(2180,1367.03) 2190.75,1367.03 2195,1362.78 J2.21
PB15_OTG_HS_P: J2.19 U1.76 | length 947.8
  Top Layer w6: U1.76 1479.92,1529.98 1483.26,1533.33 1483.26,1575.37 1510.88,1602.98 1790.38,1602.98 2008.38,1384.98 2105,1384.98 2105.04,1385.03 2175,1385.03 v1(2180,1390.03)
  Bottom Layer w6: v1(2180,1390.03) 2190.75,1390.03 2195,1394.28 J2.19
PC0_LED1: J2.72 U1.26 | length 837.7
  Top Layer w10: v1(1342.13,602.11) U1.26
  Bottom Layer w10: v1(1342.13,602.11) 1342.13,592.86 1410,524.98 1855,524.98 1905.39,575.38 J2.72
PC1_ETH_MDC: J2.71 U1.27 | length 1010.5
  Top Layer w10: U1.27 1361.81,588.17 1445,504.98 1830,504.98 1900,574.98 v1(2175,574.98)
  Bottom Layer w10: v1(2175,574.98) 2251.54,574.98 J2.71
PC2_LED2: J2.70 U1.28 | length 785.6
  Top Layer w10: v1(1381.5,601.48) U1.28
  Bottom Layer w10: v1(1381.5,601.48) 1432.99,549.98 1840,549.98 1896.89,606.87 J2.70
PC3_LED3: J2.69 U1.29 | length 970.2
  Top Layer w10: U1.29 1401.18,583.8 1460,524.98 1815,524.98 1895,604.98 v1(2175,604.98)
  Bottom Layer w10: v1(2175,604.98) 2250.04,604.98 J2.69
PC4_RMII_RXD0: J2.53 U1.44 | length 631.9
  Top Layer w10: U1.44 2172.56,867.43 v1(2180,859.98)
  Bottom Layer w10: v1(2180,859.98) 2250.79,859.98 J2.53
PC5_RMII_RXD1: J2.52 U1.45 | length 456.4
  Top Layer w10: U1.45 v1(1662.87,887.11)
  Bottom Layer w10: v1(1662.87,887.11) 2075.47,887.11 J2.52
PC6_DCMI_D0: J1.8 U1.96 | length 1158.5
  Top Layer w10: v1(185,1579.98) 365,1579.98 460,1674.98 1035,1674.98 1086.22,1623.76 U1.96
  Bottom Layer w10: J1.8 113.46,1579.98 v1(185,1579.98)
PC7_DCMI_D1: J1.9 U1.97 | length 984
  Top Layer w10: U1.97 v1(1066.54,1543.45)
  Bottom Layer w10: J1.9 386.77,1551.76 520,1684.98 1005,1684.98 1066.54,1623.45 v1(1066.54,1543.45)
PC8_SDIO_D0: J1.10 U1.98 | length 1104
  Top Layer w10: v1(185,1549.98) 375,1549.98 475,1649.98 1010,1649.98 1046.85,1613.13 U1.98
  Bottom Layer w10: J1.10 111.97,1549.98 v1(185,1549.98)
PC9_SDIO_D1: J1.11 U1.99 | length 917.8
  Top Layer w10: U1.99 v1(1027.17,1542.82)
  Bottom Layer w10: J1.11 400.28,1520.26 535,1654.98 970,1654.98 1027.17,1597.82 v1(1027.17,1542.82)
PC10_SDIO_D2: J1.29 U1.111 | length 540.9
  Top Layer w10: v1(720.75,1379.24) U1.111
  Bottom Layer w10: J1.29 406.81,1236.8 549.25,1379.24 v1(720.75,1379.24)
PC11_SDIO_D3: J1.30 U1.112 | length 704.9
  Top Layer w10: v1(180,1234.98) 400,1234.98 524.57,1359.55 U1.112
  Bottom Layer w10: J1.30@112.01,1234.98 v1(180,1234.98)
PC12_SDIO_CLK: J1.31 U1.113 | length 537.7
  Top Layer w10: v1(720.12,1339.87) U1.113
  Bottom Layer w10: J1.31 415.31,1205.3 549.88,1339.87 v1(720.12,1339.87)
PC13: J1.70 U1.7 | length 1334.3
  Top Layer w10: v1(178.78,604.98) 445,604.98 540,509.98 540,354.98 620,274.98 730,274.98 780,324.98 780,409.98 865,494.98 895,494.98 968.11,568.09 v1(968.11,601.87) U1.7
  Bottom Layer w10: J1.70 176.89,606.87 v1(178.78,604.98)
PC14: C1.1 R1.2 U1.8 X1.2 | length 396.9
  Top Layer w10: C1.1 862.2,317.23 X1.2 862.2,431.64 R1.2 ; R1.2@895.28,465.26 987.8,557.78 U1.8
PC15: C2.1 R1.1 U1.9 X1.1 | length 373.6
  Top Layer w10: C2.1 954.45,298.88 954.45,469.43 1007.48,522.46 U1.9
PD0_SMC_D2: J1.32 U1.114 | length 702.6
  Top Layer w10: v1(180,1204.98) 405,1204.98 520.2,1320.18 U1.114
  Bottom Layer w10: J1.32@110.51,1204.98 v1(180,1204.98)
PD1_SMC_D3: J1.33 U1.115 | length 534.4
  Top Layer w10: v1(720.51,1300.5) U1.115
  Bottom Layer w10: J1.33 418.82,1173.8 545.51,1300.5 v1(720.51,1300.5)
PD2_SDIO_CMD: J1.34 U1.116 | length 697.2
  Top Layer w10: v1(180,1169.98) 405,1169.98 515.83,1280.81 U1.116
  Bottom Layer w10: J1.34@114.02,1169.98 v1(180,1169.98)
PD3_CTP_SDA: J1.35 U1.117 | length 531.1
  Top Layer w10: v1(721.14,1261.13) U1.117
  Bottom Layer w10: J1.35 417.32,1142.31 536.14,1261.13 v1(721.14,1261.13)
PD4_LCD_RD: J1.36 U1.118 | length 694.9
  Top Layer w10: v1(180,1139.98) 410,1139.98 511.46,1241.44 U1.118
  Bottom Layer w10: J1.36@112.52,1139.98 v1(180,1139.98)
PD5_LCD_WR: J1.37 U1.119 | length 527.9
  Top Layer w10: v1(721.77,1221.76) U1.119
  Bottom Layer w10: J1.37 420.83,1110.81 531.77,1221.76 v1(721.77,1221.76)
PD6_CTP_RST: J1.38 U1.122 | length 676.2
  Top Layer w10: v1(180,1109.98) 415,1109.98 467.72,1162.7 U1.122
  Bottom Layer w10: J1.38@111.02,1109.98 v1(180,1109.98)
PD7_CTP_SCL: J1.39 U1.123 | length 508.3
  Top Layer w10: v1(721.97,1143.02) U1.123
  Bottom Layer w10: J1.39 434.33,1079.31 498.03,1143.02 v1(721.97,1143.02)
PD8_SMC_D13: J2.17 U1.77 | length 966.2
  Top Layer w10: U1.77 1460.24,1580.22 1500,1619.98 1805,1619.98 2000,1424.98 v1(2180,1424.98)
  Bottom Layer w10: v1(2180,1424.98) 2251.14,1424.98 J2.17
PD9_SMC_D14: J2.16 U1.78 | length 766.7
  Top Layer w10: U1.78 v1(1440.55,1544.43)
  Bottom Layer w10: v1(1440.55,1544.43) 1440.55,1560.54 1475,1594.98 1775,1594.98 1912.72,1457.27 J2.16
PD10_SDR_D10: J2.15 U1.79 | length 1018.8
  Top Layer w10: U1.79 1420.87,1590.85 1475,1644.98 1815,1644.98 2000,1459.98 v1(2180,1459.98)
  Bottom Layer w10: v1(2180,1459.98) 2249.21,1459.98 J2.15
PD11_ETH_RESET: J2.14 U1.80 | length 822.9
  Top Layer w10: U1.80 v1(1401.18,1543.8)
  Bottom Layer w10: v1(1401.18,1543.8) 1401.18,1576.17 1445,1619.98 1785,1619.98 1916.22,1488.76 J2.14
PD12_SDR_D11: J2.13 U1.81 | length 1072.1
  Top Layer w10: U1.81 1381.5,1601.48 1450,1669.98 1825,1669.98 2005,1489.98 v1(2180,1489.98)
  Bottom Layer w10: v1(2180,1489.98) 2250.71,1489.98 J2.13
PD13_SDR_D12: J2.12 U1.82 | length 876.2
  Top Layer w10: U1.82 v1(1361.81,1546.8)
  Bottom Layer w10: v1(1361.81,1546.8) 1361.81,1586.8 1420,1644.98 1795,1644.98 1919.72,1520.26 J2.12
PD14_SDR_D13: J2.11 U1.85 | length 1139
  Top Layer w10: U1.85 1302.76,1567.74 1430,1694.98 1840.28,1694.98 2015.28,1519.98 v1(2180,1519.98)
  Bottom Layer w10: v1(2180,1519.98) 2180.28,1520.26 J2.11
PD15_SDR_D14: J2.10 U1.86 | length 975.1
  Top Layer w10: U1.86 v1(1283.07,1548.06)
  Bottom Layer w10: v1(1283.07,1548.06) 1283.07,1608.06 1345,1669.98 1810,1669.98 1928.23,1551.76 J2.10
PDR_ON: R4.1 R5.1 U1.143 | length 172.6
  Top Layer w10: v1(725.67,749.31) U1.143
  Bottom Layer w10: R5.1 663.45,668.09 R4.1 682.78,749.31 v1(725.67,749.31)
PE0: J1.55 U1.141 | length 497.9
  Top Layer w10: v1(726.3,788.69) U1.141
  Bottom Layer w10: J1.55 382.64,827.35 421.3,788.69 v1(726.3,788.69)
PE1: J1.56 U1.142 | length 679.3
  Top Layer w10: v1(177.64,827.35) 377.64,827.35 435.98,769 U1.142
  Bottom Layer w10: J1.56 v1(177.64,827.35)
PE2_CTP_INT: J1.63 U1.1 | length 666
  Top Layer w10: v1(850,599.98) U1.1
  Bottom Layer w10: J1.63 483.62,701.36 600,584.98 835,584.98 v1(850,599.98)
PE3_LCD_RST: J1.64 U1.2 | length 921.5
  Top Layer w10: v1(180,699.98) 485,699.98 660,524.98 795,524.98 830,559.98 855,559.98 869.68,574.67 U1.2
  Bottom Layer w10: J1.64@111.57,699.98 v1(180,699.98)
PE4_DCMI_D4: J1.65 U1.3 | length 722.2
  Top Layer w10: v1(889.37,600.61) U1.3
  Bottom Layer w10: J1.65 485.12,669.87 595,559.98 865,559.98 889.37,584.35 v1(889.37,600.61)
PE5_DCMI_D6: J1.66 U1.4 | length 970.9
  Top Layer w10: v1(180,669.98) 485,669.98 655,499.98 800,499.98 840,539.98 875,539.98 909.06,574.04 U1.4
  Bottom Layer w10: J1.66 110.32,669.98 v1(180,669.98)
PE6_DCMI_D7: J1.67 U1.5 | length 762.5
  Top Layer w10: v1(928.74,601.24) U1.5
  Bottom Layer w10: J1.67 486.61,638.37 585,539.98 880,539.98 928.74,588.72 v1(928.74,601.24)
PE7_SMC_D4: J2.41 U1.58 | length 670.1
  Top Layer w10: U1.58 1966.97,1143.02 2065,1044.98 v1(2180,1044.98)
  Bottom Layer w10: v1(2180,1044.98) 2249.09,1044.98 J2.41
PE8_SMC_D5: J2.40 U1.59 | length 489.6
  Top Layer w10: U1.59 v1(1667.72,1162.7)
  Bottom Layer w10: v1(1667.72,1162.7) 1882.28,1162.7 1965.67,1079.31 J2.40
PE9_SMC_D6: J2.39 U1.60 | length 671
  Top Layer w10: U1.60 1977.6,1182.39 2080,1079.98 v1(2180,1079.98)
  Bottom Layer w10: v1(2180,1079.98) 2251.26,1079.98 J2.39
PE10_SMC_D7: J2.38 U1.63 | length 509.2
  Top Layer w10: U1.63 v1(1666.46,1241.44)
  Bottom Layer w10: v1(1666.46,1241.44) 1838.54,1241.44 1969.17,1110.81 J2.38
PE11_SMC_D8: J2.37 U1.64 | length 691.3
  Top Layer w10: U1.64 1933.86,1261.13 2085,1109.98 v1(2180,1109.98)
  Bottom Layer w10: v1(2180,1109.98) 2251.1,1109.98 J2.37
PE12_SMC_D9: J2.36 U1.65 | length 512.4
  Top Layer w10: U1.65 v1(1664.17,1280.81)
  Bottom Layer w10: v1(1664.17,1280.81) 1665,1279.98 1845,1279.98 1982.68,1142.31 J2.36
PE13_SMC_D10: J2.35 U1.66 | length 695.8
  Top Layer w10: U1.66 1944.49,1300.5 2105,1139.98 v1(2180,1139.98)
  Bottom Layer w10: v1(2180,1139.98) 2249.61,1139.98 J2.35
PE14_SMC_D11: J2.34 U1.67 | length 515.7
  Top Layer w10: U1.67 v1(1664.8,1320.18)
  Bottom Layer w10: v1(1664.8,1320.18) 1844.8,1320.18 1991.18,1173.8 J2.34
PE15_SMC_D12: J2.33 U1.68 | length 697.1
  Top Layer w10: U1.68 1960.12,1339.87 2125,1174.98 v1(2180,1174.98)
  Bottom Layer w10: v1(2180,1174.98) 2250.75,1174.98 J2.33
PF0_SDR_A10: J1.74 U1.10 | length 1557.2
  Top Layer w10: v1(180,544.98) 460,544.98 520,484.98 520,334.98 605,249.98 1040,249.98 1060,269.98 1060,384.98 1027.17,417.82 U1.10
  Bottom Layer w10: J1.74 178.9,543.88 v1(180,544.98)
PF1_SDR_A0: J1.75 U1.11 | length 1367.2
  Top Layer w10: v1(1046.85,601.83) U1.11
  Bottom Layer w10: J1.75 487.6,512.39 515,484.98 515,344.98 620,239.98 1035,239.98 1060,264.98 1060,588.68 v1(1046.85,601.83)
PF2_SDR_A1: J1.76 U1.12 | length 1573
  Top Layer w10: v1(180,509.98) 440,509.98 495,454.98 495,324.98 595,224.98 1050,224.98 1080,254.98 1080,399.98 1066.54,413.45 U1.12
  Bottom Layer w10: J1.76 112.6,509.98 v1(180,509.98)
PF3_SDR_A2: J1.77 U1.13 | length 1389.6
  Top Layer w10: v1(1086.22,601.2) U1.13
  Bottom Layer w10: J1.77 459.09,480.89 490,449.98 490,334.98 610.67,214.32 1049.33,214.32 1086.22,251.2 v1(1086.22,601.2)
PF4_SDR_A3: J1.78 U1.14 | length 1612.7
  Top Layer w10: v1(180,479.98) 435.91,479.98 470,445.89 470,309.98 580,199.98 1065,199.98 1105.91,240.89 U1.14
  Bottom Layer w10: J1.78 111.1,479.98 v1(180,479.98)
PF5_SPI_CS: J1.79 U1.15 | length 1429.4
  Top Layer w10: v1(1125.59,600.57) U1.15
  Bottom Layer w10: J1.79 445.59,449.39 465,429.98 465,319.98 590,194.98 1070,194.98 1125.59,250.57 v1(1125.59,600.57)
PF6_SDR_A4: J2.78 U1.18 | length 1692.5
  Top Layer w10: v1(1184.65,600.34) U1.18
  Bottom Layer w10: v1(1184.65,600.34) 1184.65,513.2 1150,478.56 1150,164.98 1190,124.98 1755,124.98 1870,239.98 1870,419.98 1930.91,480.89 J2.78
PF7_SDR_A5: J2.77 U1.19 | length 1845.8
  Top Layer w10: U1.19 1204.33,504.32 1130,429.98 1130,189.98 1180,139.98 1735,139.98 1855,259.98 1855,389.98 1945,479.98 v1(2175,479.98)
  Bottom Layer w10: v1(2175,479.98) 2251.02,479.98 J2.77
PF8_SDR_A6: J2.76 U1.20 | length 1654.1
  Top Layer w10: v1(1224.02,600.97) U1.20
  Bottom Layer w10: v1(1224.02,600.97) 1224.02,504 1175,454.98 1175,184.98 1210,149.98 1740,149.98 1845,254.98 1845,434.98 1922.4,512.39 J2.76
PF9_SDR_A7: J2.75 U1.21 | length 1817.4
  Top Layer w10: U1.21 1243.7,508.68 1150,414.98 1150,204.98 1190,164.98 1725,164.98 1825,264.98 1825,394.98 1930,499.98 2165,499.98 v1(2175,509.98)
  Bottom Layer w10: v1(2175,509.98) 2177.4,512.39 J2.75
PF10_SDR_A8: J2.74 U1.22 | length 1631.5
  Top Layer w10: v1(1263.39,601.6) U1.22
  Bottom Layer w10: v1(1263.39,601.6) 1263.39,500 1200,436.62 1200,189.98 1220,169.98 1725,169.98 1820,264.98 1820,449.98 1913.9,543.88 J2.74
PF11_SDR_UDQM: J2.48 U1.49 | length 460.3
  Top Layer w10: U1.49 v1(1664.13,965.85)
  Bottom Layer w10: v1(1664.13,965.85) 1864.13,965.85 1876.65,953.33 J2.48
PF12_KEY3: J2.47 U1.50 | length 644.4
  Top Layer w10: U1.50 1952.8,985.54 1988.35,949.98 v1(2180,949.98)
  Bottom Layer w10: v1(2180,949.98) 2183.35,953.33 J2.47
PF13_CAMER_RST: J2.46 U1.53 | length 479.8
  Top Layer w10: U1.53 v1(1664.61,1044.59)
  Bottom Layer w10: v1(1664.61,1044.59) 1845.39,1044.59 1905.16,984.83 J2.46
PF14_LCD_BK: J2.45 U1.54 | length 661.2
  Top Layer w10: U1.54 1935.71,1064.28 2015,984.98 v1(2180,984.98)
  Bottom Layer w10: v1(2180,984.98) 2251.77,984.98 J2.45
PF15_485_EN: J2.44 U1.55 | length 483.1
  Top Layer w10: U1.55 v1(1663.98,1083.96)
  Bottom Layer w10: v1(1663.98,1083.96) 1863.98,1083.96 1931.61,1016.32 J2.44
PG0: J2.43 U1.56 | length 665.6
  Top Layer w10: U1.56 1950.98,1103.65 2039.65,1014.98 v1(2180,1014.98)
  Bottom Layer w10: v1(2180,1014.98) 2181.34,1016.32 J2.43
PG1_SDR_CLK: J2.42 U1.57 | length 486.4
  Top Layer w10: U1.57 v1(1666.65,1123.33)
  Bottom Layer w10: v1(1666.65,1123.33) 1876.65,1123.33 1952.17,1047.82 J2.42
PG2_SDR_D15: J2.9 U1.87 | length 1184.7
  Top Layer w10: U1.87 1263.39,1563.37 1420,1719.98 1855,1719.98 2025,1549.98 v1(2180,1549.98)
  Bottom Layer w10: v1(2180,1549.98) 2250.16,1549.98 J2.9
PG3_SDR_D0: J2.8 U1.88 | length 1027.1
  Top Layer w10: U1.88 v1(1243.7,1548.69)
  Bottom Layer w10: v1(1243.7,1548.69) 1243.7,1623.69 1310,1689.98 1830,1689.98 1936.73,1583.25 J2.8
PG4_SDR_D1: J2.7 U1.89 | length 1236.3
  Top Layer w10: U1.89 1224.02,1569 1400,1744.98 1865,1744.98 2030,1579.98 v1(2180,1579.98)
  Bottom Layer w10: v1(2180,1579.98) 2248.66,1579.98 J2.7
PG5_SDR_D2: J2.6 U1.90 | length 1081.6
  Top Layer w10: U1.90 v1(1204.33,1549.31)
  Bottom Layer w10: v1(1204.33,1549.31) 1204.33,1629.31 1295,1719.98 1845,1719.98 1950.24,1614.75 J2.6
PG6_SDR_D3: J2.5 U1.91 | length 1284.9
  Top Layer w10: U1.91 1184.65,1569.63 1385,1769.98 1879.76,1769.98 2039.76,1609.98 v1(2180,1609.98)
  Bottom Layer w10: v1(2180,1609.98) 2247.17,1609.98 J2.5
PG7_BUZ: J2.3 U1.92 | length 1321.2
  Top Layer w10: U1.92 1164.96,1589.94 1370,1794.98 1890,1794.98 2040,1644.98 v1(2180,1644.98)
  Bottom Layer w10: v1(2180,1644.98) 2181.26,1646.24 J2.3
PG8_SDR_D4: J1.7 U1.93 | length 1069.9
  Top Layer w10: U1.93 v1(1145.28,1544.71)
  Bottom Layer w10: J1.7 373.27,1583.25 495,1704.98 1070,1704.98 1145.28,1629.71 v1(1145.28,1544.71)
PG9_LCD_RS: J1.40 U1.124 | length 673.4
  Top Layer w10: v1(180,1079.98) 425,1079.98 468.35,1123.33 U1.124
  Bottom Layer w10: J1.40 179.33,1079.31 v1(180,1079.98)
PG10_LCD_CS: J1.41 U1.125 | length 505.1
  Top Layer w10: v1(721.34,1103.65) U1.125
  Bottom Layer w10: J1.41 442.83,1047.82 498.66,1103.65 v1(721.34,1103.65)
PG11_RMII_TX_EN: J1.42 U1.126 | length 668.5
  Top Layer w10: v1(180,1044.98) 430,1044.98 468.98,1083.96 U1.126
  Bottom Layer w10: J1.42@113.03,1044.98 v1(180,1044.98)
PG12: J1.43 U1.127 | length 501.8
  Top Layer w10: v1(720.71,1064.28) U1.127
  Bottom Layer w10: J1.43 451.34,1016.32 499.29,1064.28 v1(720.71,1064.28)
PG13_RMII_TXD0: J1.44 U1.128 | length 668
  Top Layer w10: v1(180,1014.98) 430,1014.98 459.61,1044.59 U1.128
  Bottom Layer w10: J1.44 111.54,1014.98 v1(180,1014.98)
PG14_RMII_TXD1: J1.45 U1.129 | length 498.6
  Top Layer w10: v1(720,1024.91) U1.129
  Bottom Layer w10: J1.45 454.84,984.83 495,1024.98 719.92,1024.98 v1(720,1024.91)
PG15_SDR_LDQM: J1.46 U1.132 | length 663.1
  Top Layer w10: v1(180,984.98) 430,984.98 449.13,965.85 U1.132
  Bottom Layer w10: J1.46 179.84,984.83 v1(180,984.98)
PH0: C3.1 R3.2 U1.23 X2.3 | length 479.7
  Top Layer w10: C3.1@1254.45,234.98 1251.69,237.74 1251.69,301.52 1238.46,301.52 1205,334.98 1205,409.98 1250,454.98 R3.2 1283.07,472.5 U1.23
PH1: C4.1 R3.1 U1.24 X2.1 | length 464.5
  Top Layer w10: U1.24 1302.76,486.68 R3.1 1334.45,372.31 1338.31,368.45 1366.54,368.45 1394.45,340.54 C4.1@1394.45,234.98
RESET: C5.1 J2.73 R6.1 S1.1 U1.25 | length 1293.2
  Top Layer w10: U1.25 1322.44,582.54 1430,474.98 1575,474.98 C5.1@1615,434.98 ; C5.1 R6.1 ; S1.1 1665.55,407.39 R6.1 ; v1(2175,544.98) 2165,554.98 1910,554.98 1830,474.98 1685,474.98 1665.55,455.54 R6.1
  Bottom Layer w10: v1(2175,544.98) 2250.83,544.98 J2.73
VBAT_IN: C8.1 J1.68 U1.6 | length 1337.4
  Top Layer w10: v1(180,639.98) 470,639.98 565,544.98 565,364.98 630,299.98 720,299.98 755,334.98 755,454.98 790,454.98 850,514.98 885,514.98 948.43,578.41 U1.6
  Bottom Layer w10: J1.68 178.39,638.37 v1(180,639.98)
pads on no net: H1.1 H2.1 H3.1 H4.1 J1.18 J1.19 J1.20 J1.21 J1.22 J1.25 J1.26 J1.57 J1.58 J1.59 J1.60 J1.69 J1.71 J1.72 J1.73 J1.81 J1.82 J2.22 J2.25 J2.26 J2.27 J2.28 J2.29 J2.30 J2.59 J2.60 J2.64 J2.65 J2.81 J2.82
copper on no net: | length 2473.7
  Top Layer w11.81: 324.21,-125 ccw(c275,-125) 324.21,-125 ; 363.69,2214.87 ccw(c314.48,2214.87) 363.69,2214.87 ; 2094.73,-89.87 ccw(c2045.52,-89.87) 2094.73,-89.87 ; 2134.21,2250 ccw(c2085,2250) 2134.21,2250
  Bottom Layer w11.81: 323.82,-124.61 ccw(c274.61,-124.61) 323.82,-124.61 ; 363.3,2215.27 ccw(c314.08,2215.27) 363.3,2215.27 ; 2095.13,-90.27 ccw(c2045.92,-90.27) 2095.13,-90.27 ; 2134.61,2249.61 ccw(c2085.39,2249.61) 2134.61,2249.61

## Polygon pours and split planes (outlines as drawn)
GND on Top Layer "Top Overlay-No Net" (solid, remove dead copper, pour order 15): 150,2104.98 100,2104.98 75,2104.98 20,2049.98 20,79.98 20,74.98 75,19.98 115,19.98 2280,19.98 2340,79.98 2340,154.98 2340,2004.98 2340,2024.98 2340,2049.98 2285,2104.98 150,2104.98
GND on Bottom Layer "Top Overlay-No Net" (solid, remove dead copper, pour order 21): 75,2104.98 20,2049.98 20,74.98 75,19.98 2280,19.98 2340,79.98 2340,2049.98 2285,2104.98 75,2104.98

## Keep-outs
Keep-Out Layer:
  circle w7.87: c2242.37,-129.24 r39.37
  circle w7.87: c78.15,-85.63 r39.37
  circle w7.87: c2281.85,2210.63 r39.37
  circle w7.87: c117.63,2254.24 r39.37
  lines w7.87: 0,2125 0,2342.67 2360,2342.67 2360,2125 ; 0.03,2124.97 175,2124.97 ; 967.18,2125 1176.35,2125 ; 1392.81,0 1183.65,0 ; 2185,0.03 2359.97,0.03 ; 2360,0 2360,-217.67 0,-217.67 0,0 ; 0,0 1183.65,0 ; 0,0 1183.65,0 ; 1176.35,2125 2360,2125 ; 1176.35,2125 2360,2125
  lines w10: 100,0.03 2260,0.03 ; 100,2124.97 2260,2124.97 ; 100,2124.98 ccw(c100,2024.98) 0,2024.98 0,99.98 ccw(c100,99.98) 100,-0.02 ; 2260,2124.98 cw(c2260,2024.98) 2360,2024.98 ; 2360,2029.98 2360,99.98 ; 100,-0.02 2260,-0.02 ; 100,-0.02 2260,-0.02 ; 2260,-0.02 ccw(c2260,99.98) 2360,99.98 ; 2360,99.98 2360,2024.98 ; 2360,99.98 2360,2024.98

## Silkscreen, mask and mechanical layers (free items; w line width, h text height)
Top Overlay:
  drawing of 4272 lines, arcs and shapes, not listed
  text "APM32F407ZG Core V1" at 650,1865 h98.43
